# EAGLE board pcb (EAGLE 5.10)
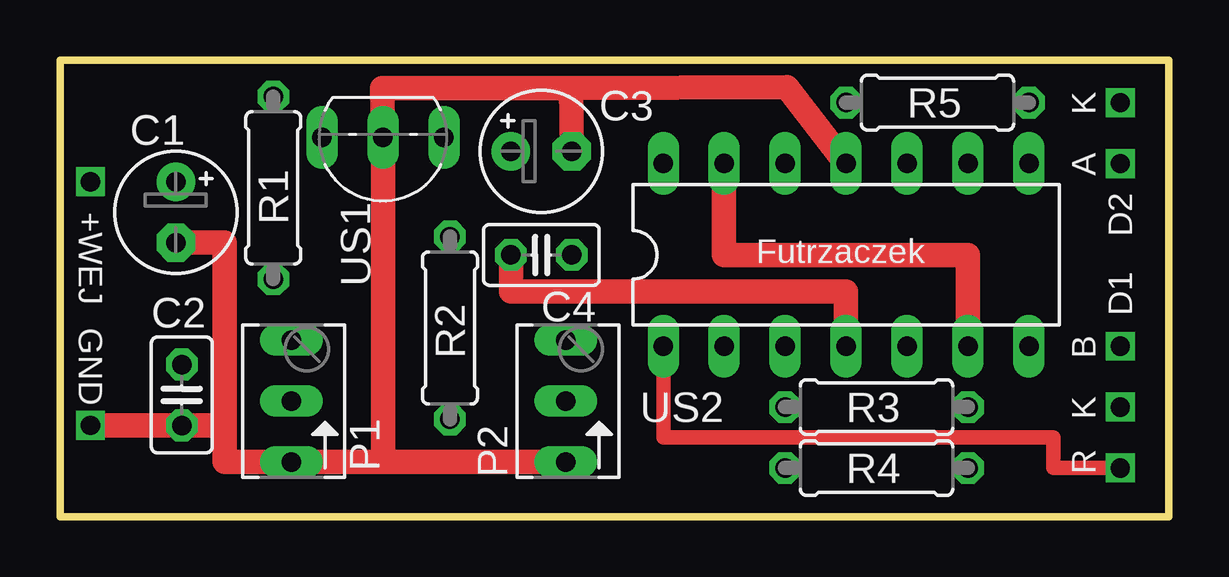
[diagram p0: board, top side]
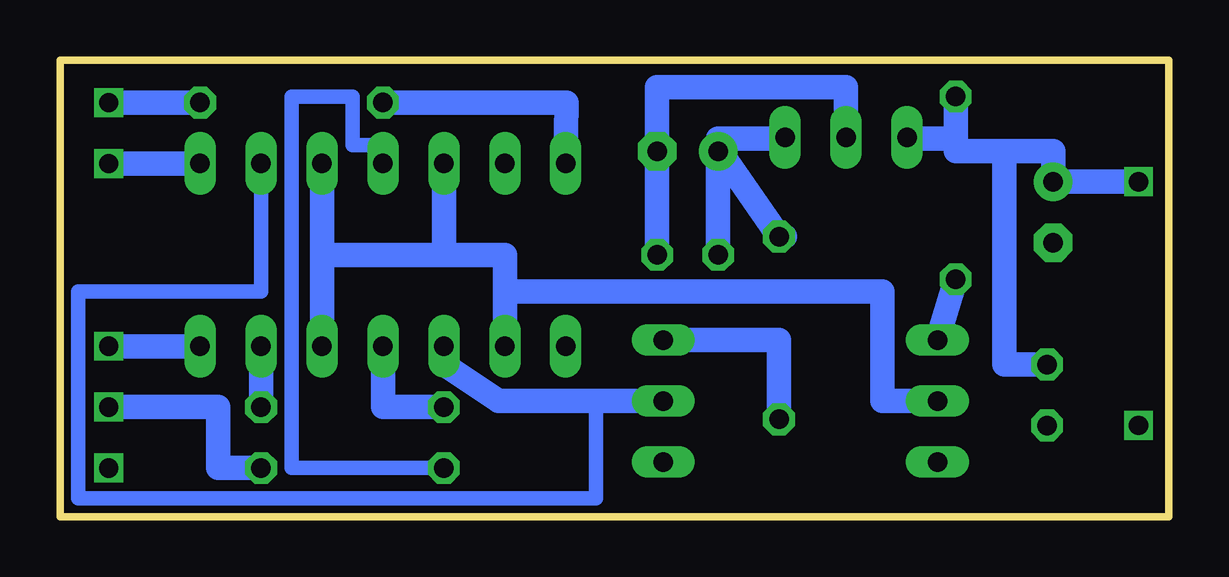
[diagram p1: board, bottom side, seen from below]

Size 46.23 x 19.05 mm. Coordinates in mm from the lower left corner, seen from the top.
Outline: 46.23,19.05 46.23,0 0,0 0,19.05 46.23,19.05
Copper layers (1*16): Top 0.035mm / dielectric 1.5mm / Bottom 0.035mm
Design rules "default": minimum track width 10mil, minimum drill 24mil, track to track 8mil, track to pad 8mil, pad to pad 8mil, via to via 8mil, smd to smd 8mil, copper to edge 40mil, drill to drill 8mil, minimum pad ring 10mil, minimum via ring 8mil, stop-mask expansion 4mil, vias tented up to drill 0mil, thermal gap 10mil

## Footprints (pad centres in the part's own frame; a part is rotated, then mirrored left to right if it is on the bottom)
E2,5-5 = drill 0.813 pad 1.6 round: + -1.27,0 | drill 0.813 pad 1.6 octagon: - 1.27,0
C025-025X050 = drill 0.813 octagon: 1 -1.27,0; 2 1.27,0
B64Y = drill 0.813 long: A 2.54,0; E -2.54,0; S 0,0
0207/7 = drill 0.813 octagon: 1 -3.81,0; 2 3.81,0
TO92-BCE = drill 0.813 long: B 2.54,0; C 0,0; E -2.54,0
DIL14 = drill 0.813 long: 1 -7.62,-3.81; 2 -5.08,-3.81; 3 -2.54,-3.81; 4 0,-3.81; 5 2.54,-3.81; 6 5.08,-3.81; 7 7.62,-3.81; 8 7.62,3.81; 9 5.08,3.81; 10 2.54,3.81; 11 0,3.81; 12 -2.54,3.81; 13 -5.08,3.81; 14 -7.62,3.81

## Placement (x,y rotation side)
C1  [E2,5-5]  4.83,12.7 270 top
C2  [C025-025X050]  5.08,5.08 90 top
C3  [E2,5-5]  20.07,15.24 0 top
C4  [C025-025X050]  20.07,10.92 180 top
P1  [B64Y]  9.65,4.83 90 top
P2  [B64Y]  21.08,4.83 90 top
R1  [0207/7]  8.89,13.72 90 top
R2  [0207/7]  16.26,7.87 90 top
R3  [0207/7]  34.04,4.57 180 top
R4  [0207/7]  34.04,2.03 180 top
R5  [0207/7]  36.58,17.27 0 top
US1  [TO92-BCE]  13.46,15.83 180 top
US2  [DIL14]  32.77,10.92 0 top

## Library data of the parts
C1-C4 = rcl
P1 P2 = pot
R1-R5 = resistor
US1 = transistor-npn
US2 = 40xx

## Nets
S$1: US2.2 US2.5 US2.10 US2.12
S$2: R3.1 US2.6 US2.13
S$3: C4.2 R3.2 US2.4
S$4: US2.8
S$5: R5.2
S$6: US2.7
S$7: R4.1
S$9: R5.1 US2.14
S$10: R4.2
S$11: US2.1
S$12: P2.A R2.1
S$14: C1.- C3.- C4.1 P1.E P2.E US1.C US2.11
S$15: R2.2
S$16: US2.3
S$17: C1.+ C2.2 R1.2
S$18: P1.A R1.1
S$21: P1.S

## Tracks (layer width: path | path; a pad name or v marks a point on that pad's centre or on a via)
S$1
  Bottom 1.016: 35.31,10.92 US2.5 | 35.31,10.92 US2.10 | 27.69,9.4 23.11,9.4 | 30.23,10.92 35.31,10.92 | 30.23,10.92 US2.12 | 30.23,10.92 27.69,10.92 27.69,9.4 | US2.2 27.69,9.4
S$2
  Top 1.016: US2.6 37.85,10.92 27.69,10.92 US2.13
  Bottom 1.016: R3.1 US2.6
S$3
  Top 1.016: US2.4 32.77,9.4 18.8,9.4 C4.2
  Bottom 1.016: R3.2 32.77,4.57 US2.4 | C4.2 18.8,13.89 18.8,15.24 18.8,15.77 16.05,15.77
S$4  (via drill 0.8)
  Bottom 1.016: US2.8 v44.2,14.73
S$5  (via drill 0.8)
  Bottom 1.016: R5.2 v44.2,17.27
S$6  (via drill 0.8)
  Bottom 1.016: US2.7 v44.2,7.11
S$7  (via drill 0.8)
  Bottom 1.016: v44.2,4.57 39.62,4.57 39.62,2.03 R4.1
S$8  (via drill 0.8)
  other vias: 44.2,2.03
S$9
  Bottom 1.016: US2.14 25.12,17.27 R5.1
S$10
  Bottom 0.61: 32.77,15.49 34.04,15.49 34.04,17.53 36.58,17.53 36.58,2.03 R4.2
S$11
  Top 0.61: 43.94,2.03 41.4,2.03 41.4,3.3 25.15,3.3 US2.1
S$12
  Bottom 1.016: P2.A 16.26,7.37 R2.1
S$13
  Bottom 0.61: 37.85,14.48 37.85,9.4 45.47,9.4 45.47,0.76 23.88,0.76 23.88,4.57
S$14
  Top 1.016: US2.11 30.3,17.91 21.31,17.88 | 21.31,17.88 C3.- | C1.- 6.86,11.43 6.86,3.81 | 6.86,3.81 6.86,2.29 P1.E 13.46,2.29 | P2.E 13.46,2.29 | 13.46,2.29 US1.C 13.44,17.88 21.31,17.88 | 6.86,3.81 1.27,3.81
  Bottom 1.016: C4.1 21.34,17.91 13.46,17.91 US1.C
S$15
  Bottom 1.016: R2.2 16,11.68
S$16
  Bottom 1.016: US2.3 30.23,6.35 27.94,4.83 20.83,4.83
S$17  (via drill 0.8)
  Bottom 1.016: v1.27,13.97 C1.+ 4.83,15.24 6.86,15.24 | 8.89,15.77 8.89,15.24 6.86,15.24 | 8.89,15.77 R1.2 | 6.86,15.24 6.86,6.35 C2.2 | 10.9,15.77 8.89,15.77
S$18
  Bottom 1.016: R1.1 P1.A
S$19
  Bottom 1.016: 16.23,11.66 18.77,15.34
S$20  (via drill 0.8)
  other vias: 1.27,3.81
S$21
  Bottom 1.016: 23.62,9.4 11.94,9.4 11.94,4.83 P1.S

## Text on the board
tNames: K | A | +WEJ | D2 | Futrzaczek | GND | D1 | B | K | R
